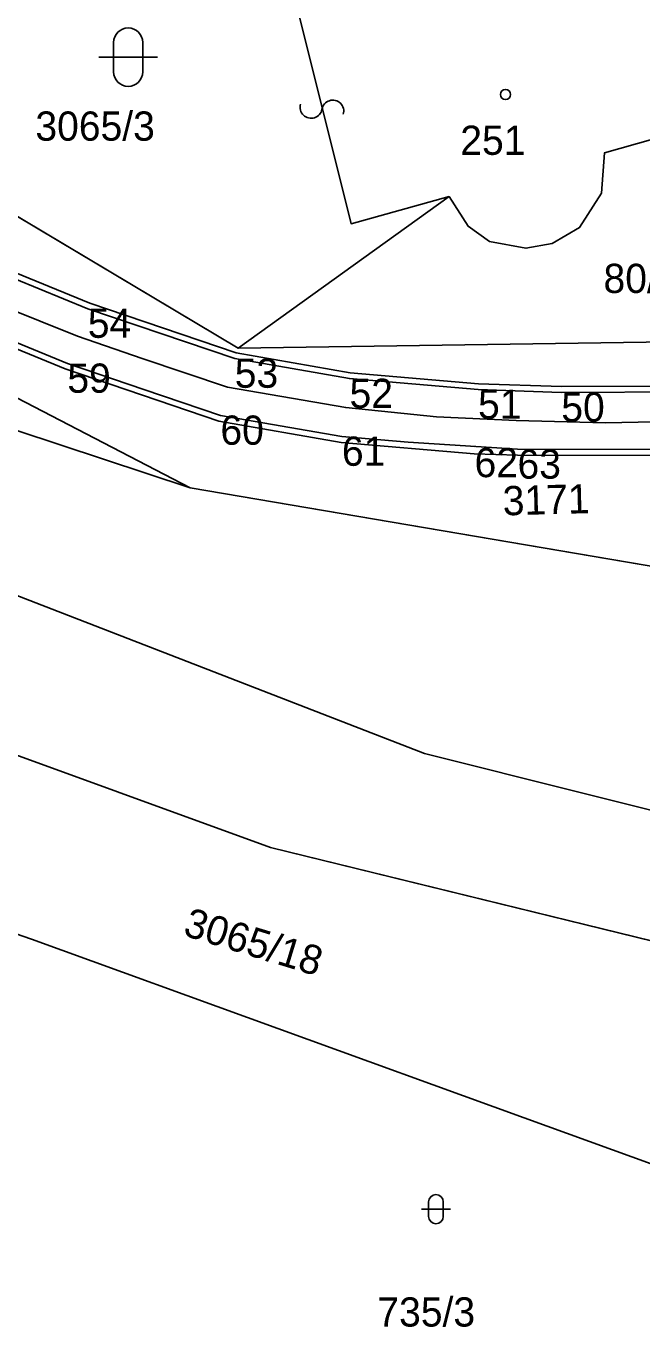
# Model space of a CAD drawing. Extents: x -728800 to -728100, y -1073200 to -1072700.
# Drawn here: x -728549.49 to -728528.4, y -1073055.63 to -1073011.1 of the extents above; entities that cross this region are included whole.
import ezdxf

# ---------------------------------------------------------------- set-up
doc = ezdxf.new("R2010")
doc.units = 0
for name, color, linetype in [('A1_OBVOD Spravy železnic', 7, 'Continuous'), ('A2_OBVOD STAVBY', 7, 'Continuous'), ('B1_body_poloha', 7, 'Continuous'), ('B2_body_číslo', 7, 'Continuous'), ('B6_JŽM', 7, 'Continuous'), ('K_01_Hranice parcel', 7, 'Continuous'), ('K_02_Parcelní čísla', 7, 'Continuous'), ('K_03_Značky druhu pozemku', 7, 'Continuous'), ('KOS_kabelová trasa VO', 7, 'Continuous'), ('ZA_02_Dočasný_do_1_roku', 7, 'Continuous')]:
    doc.layers.add(name, color=color, linetype=linetype)

msp = doc.modelspace()

# ---------------------------------------------------------------- linework, layer by layer
at = {"layer": 'A1_OBVOD Spravy železnic'}
msp.add_lwpolyline([(-728604.14, -1072988.92), (-728582.13, -1073004.22), (-728556.03, -1073020.59), (-728543.86, -1073026.9), (-728510.71, -1073032.54), (-728510.22, -1073036.28), (-728509.42, -1073042.19), (-728509.9, -1073046.86), (-728541.12, -1073039.22), (-728572.55, -1073027.78), (-728581.66, -1073022.5), (-728594.83, -1073014.86), (-728598.74, -1073012.6)], dxfattribs=at)
at = {"layer": 'A2_OBVOD STAVBY'}
for points in [[(-728509.455, -1073035.234), (-728510.689, -1073028.502), (-728511.933, -1073022.707), (-728511.986, -1073020.002), (-728513.157, -1073020.217), (-728515.255, -1073019.379), (-728517.216, -1073018.59), (-728517.096, -1073019.442), (-728517.727, -1073020.685), (-728519.2, -1073021.56), (-728519.78, -1073021.597), (-728522.531, -1073023.408), (-728531.159, -1073023.437), (-728533.997, -1073023.341), (-728538.386, -1073022.967), (-728542.291, -1073022.287), (-728547.296, -1073020.586), (-728553.966, -1073017.86)], [(-728556.425, -1073019.431), (-728548.14, -1073022.833), (-728542.882, -1073024.621), (-728538.694, -1073025.349), (-728534.14, -1073025.737), (-728532.664, -1073025.787), (-728522.232, -1073025.806), (-728521.488, -1073028.32), (-728521.545, -1073030.726), (-728521.594, -1073032.788), (-728517.755, -1073032.879), (-728517.209, -1073045.129)]]:
    msp.add_lwpolyline(points, dxfattribs=at)
at = {"layer": 'B1_body_poloha'}
for p, q in [((-728547.37, -1073020.77), (-728547.37, -1073020.77)), ((-728542.34, -1073022.48), (-728542.34, -1073022.48)), ((-728548.07, -1073022.65), (-728548.07, -1073022.65)), ((-728538.41, -1073023.17), (-728538.41, -1073023.17)), ((-728534.01, -1073023.54), (-728534.01, -1073023.54)), ((-728531.16, -1073023.64), (-728531.16, -1073023.64)), ((-728542.83, -1073024.43), (-728542.83, -1073024.43)), ((-728538.67, -1073025.15), (-728538.67, -1073025.15)), ((-728534.13, -1073025.54), (-728534.13, -1073025.54)), ((-728532.66, -1073025.59), (-728532.66, -1073025.59))]:
    msp.add_line(p, q, dxfattribs=at)
at = {"layer": 'B6_JŽM'}
msp.add_lwpolyline([(-728300.809, -1073024.355), (-728320.8, -1073026.914), (-728374.008, -1073033.722), (-728429.095, -1073040.747), (-728461.932, -1073044.273), (-728481.199, -1073044.815), (-728499.353, -1073043.648), (-728506.01, -1073042.737), (-728514.574, -1073041.329), (-728535.848, -1073035.998), (-728561.353, -1073026.113), (-728583.963, -1073013.524), (-728603.757, -1072998.891), (-728619.185, -1072984.418), (-728634.193, -1072966.825), (-728646.078, -1072949.194), (-728656.182, -1072930.072), (-728664.987, -1072910.227), (-728668.627, -1072901.808), (-728681.252, -1072876.016), (-728691.886, -1072859.663)], dxfattribs=at)
at = {"layer": 'K_01_Hranice parcel'}
for p, q in [((-728542.221, -1073022.127), (-728593.93, -1072991.26)), ((-728546.487, -1073011.663), (-728546.487, -1073012.663)), ((-728545.487, -1073011.663), (-728545.487, -1073012.663)), ((-728546.987, -1073012.163), (-728544.987, -1073012.163)), ((-728542.221, -1073022.127), (-728535.002, -1073016.936)), ((-728541.12, -1073039.22), (-728509.9, -1073046.86))]:
    msp.add_line(p, q, dxfattribs=at)
for points in [[(-728515.236, -1073016.2), (-728517.295, -1073016.589), (-728516.889, -1073019.476), (-728517.575, -1073020.827), (-728519.139, -1073021.757), (-728519.714, -1073021.793), (-728542.221, -1073022.127), (-728593.93, -1072991.26)], [(-728540.332, -1073009.948), (-728538.355, -1073017.863), (-728535.002, -1073016.936), (-728534.351, -1073017.951), (-728533.616, -1073018.472), (-728532.371, -1073018.702), (-728531.47, -1073018.542), (-728530.537, -1073017.994), (-728529.78, -1073016.821), (-728529.681, -1073015.434), (-728526.895, -1073014.649), (-728528.333, -1073007.34)], [(-728564.68, -1073020.02), (-728543.86, -1073026.9), (-728514.39, -1073031.91)], [(-728581.66, -1073022.5), (-728572.55, -1073027.78), (-728541.12, -1073039.22)], [(-728581.13, -1073030.83), (-728573.14, -1073034.08), (-728549.3, -1073042.35), (-728532.43, -1073048.47), (-728519.8, -1073053.05)]]:
    msp.add_lwpolyline(points, dxfattribs=at)
for centre, start, end in [((-728545.987, -1073011.663), 0, 180), ((-728545.987, -1073012.663), 180, 0)]:
    msp.add_arc(centre, 0.5, start, end, dxfattribs=at)
at = {"layer": 'K_03_Značky druhu pozemku'}
for p, q in [((-728535.701, -1073051.345), (-728535.701, -1073051.845)), ((-728535.201, -1073051.345), (-728535.201, -1073051.845)), ((-728535.951, -1073051.595), (-728534.951, -1073051.595))]:
    msp.add_line(p, q, dxfattribs=at)
msp.add_circle((-728533.07, -1073013.441), 0.175, dxfattribs=at)
for centre, radius, start, end in [((-728538.983, -1073014.011), 0.376, 343.6047, 169.9018), ((-728539.724, -1073013.879), 0.376, 163.6047, 349.9018), ((-728535.451, -1073051.345), 0.25, 0, 180), ((-728535.451, -1073051.845), 0.25, 180, 0)]:
    msp.add_arc(centre, radius, start, end, dxfattribs=at)
at = {"layer": 'KOS_kabelová trasa VO'}
msp.add_lwpolyline([(-728561.457, -1073013.169), (-728562.506, -1073015.027), (-728558.898, -1073016.89), (-728555.929, -1073018.337), (-728552.96, -1073019.584), (-728550.284, -1073020.683), (-728547.718, -1073021.71), (-728545.504, -1073022.477), (-728542.587, -1073023.454), (-728538.54, -1073024.158), (-728535.432, -1073024.48), (-728532.705, -1073024.598), (-728529.651, -1073024.677), (-728525.747, -1073024.604), (-728522.277, -1073024.607), (-728519.905, -1073023.659), (-728515.301, -1073022.774)], dxfattribs=at)
at = {"layer": 'ZA_02_Dočasný_do_1_roku'}
for points in [[(-728554.047, -1073018.043), (-728547.366, -1073020.773), (-728542.341, -1073022.482), (-728538.412, -1073023.165), (-728534.009, -1073023.54), (-728531.162, -1073023.637), (-728526.817, -1073023.623)], [(-728522.083, -1073025.607), (-728532.66, -1073025.587), (-728536.398, -1073025.344), (-728538.668, -1073025.15), (-728542.832, -1073024.426), (-728545.451, -1073023.536), (-728548.07, -1073022.646), (-728552.206, -1073020.947)]]:
    msp.add_lwpolyline(points, dxfattribs=at)

# ---------------------------------------------------------------- texts
at = {"layer": 'B2_body_číslo'}
for s, p in [('54', (-728547.37, -1073021.77)), ('53', (-728542.34, -1073023.48)), ('59', (-728548.07, -1073023.65)), ('52', (-728538.41, -1073024.17)), ('51', (-728534.01, -1073024.54)), ('50', (-728531.16, -1073024.64)), ('60', (-728542.83, -1073025.43)), ('61', (-728538.67, -1073026.15)), ('62', (-728534.13, -1073026.54)), ('63', (-728532.66, -1073026.59))]:
    msp.add_text(s, height=1, dxfattribs=at).set_placement(p)
at = {"layer": 'K_02_Parcelní čísla'}
for s, p in [('3065/3', (-728549.165, -1073015.022)), ('251', (-728534.618, -1073015.507)), ('80/2', (-728529.716, -1073020.235)), ('735/3', (-728537.457, -1073055.614))]:
    msp.add_text(s, height=1, dxfattribs=at).set_placement(p)
for s, rotation, p in [('3171', 1.5237, (-728533.153, -1073027.85)), ('3065/18', 343, (-728544.145, -1073042.213))]:
    msp.add_text(s, height=1, rotation=rotation, dxfattribs=at).set_placement(p)

doc.saveas('drawing.dxf')
